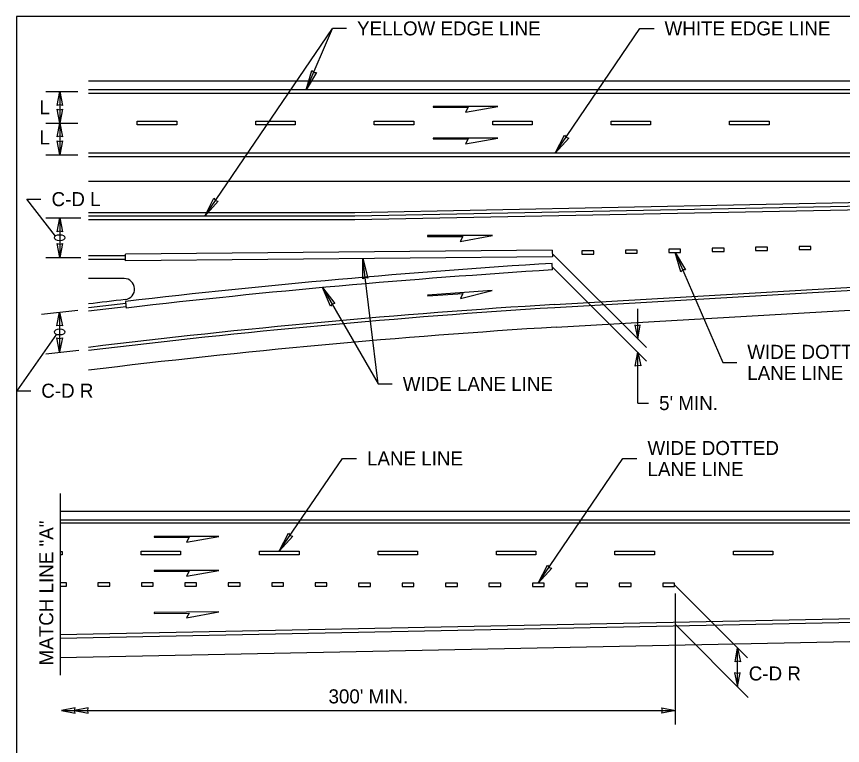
# Model space of a CAD drawing. Extents: x 99862 to 103151, y 100000 to 102076.
# Drawn here: x 99862 to 100803, y 101245 to 102076 of the extents above; entities that cross this region are included whole.
import ezdxf

# ---------------------------------------------------------------- set-up
doc = ezdxf.new("R2010")
doc.units = 0
for name, color, linetype in [('Level 1', 7, 'Continuous'), ('Level 15', 7, 'Continuous'), ('Level 2', 7, 'Continuous'), ('Level 20', 7, 'Continuous'), ('Level 3', 7, 'Continuous'), ('Level 4', 7, 'Continuous'), ('Level 5', 7, 'Continuous'), ('Level 6', 7, 'Continuous'), ('Level 7', 7, 'Continuous')]:
    doc.layers.add(name, color=color, linetype=linetype)

msp = doc.modelspace()

# ---------------------------------------------------------------- linework, layer by layer
at = {"layer": 'Level 1'}
msp.add_lwpolyline([(99862, 99999.5), (103151, 99999.5), (103151, 102075.5), (99862, 102075.5)], close=True, dxfattribs=at)
at = {"layer": 'Level 15'}
for p, q in [((100076.57, 101847.86), (100222.08, 102061.99)), ((100192.18, 101991.87), (100222.08, 102061.99)), ((100238.08, 102061.99), (100222.08, 102061.99)), ((100238.08, 102061.99), (100222.08, 102061.99)), ((100475.99, 101919.87), (100572.56, 102061.99)), ((100572.56, 102061.99), (100588.56, 102061.99)), ((100572.56, 102061.99), (100588.56, 102061.99)), ((99895.23, 101989.99), (99931.96, 101989.99)), ((99895.23, 101989.99), (99931.96, 101989.99)), ((99911.23, 101989.99), (99911.23, 101954.14)), ((99911.23, 101989.99), (99911.23, 101954.14)), ((99895.23, 101954.14), (99931.96, 101954.14)), ((99895.23, 101954.14), (99931.96, 101954.14)), ((99911.23, 101954.14), (99911.23, 101917.99)), ((99911.23, 101954.14), (99911.23, 101917.99)), ((99895.23, 101917.99), (99931.96, 101917.99)), ((99895.23, 101917.99), (99931.96, 101917.99)), ((99873.9, 101867.45), (99889.9, 101867.45)), ((99906.26, 101825.43), (99873.9, 101867.45)), ((99895.23, 101845.99), (99935.34, 101845.99)), ((99911.23, 101845.99), (99911.23, 101800.99)), ((99911.23, 101845.99), (99911.23, 101800.99)), ((100472.59, 101805.49), (100579.83, 101698.25)), ((100612.82, 101806.74), (100666.86, 101681.45)), ((99895.23, 101800.99), (99935.34, 101800.99)), ((100274.16, 101656.97), (100256.69, 101799.75)), ((100472.59, 101790.49), (100580.14, 101682.94)), ((100210.83, 101766.66), (100274.16, 101656.97)), ((99890.52, 101736.36), (99931.8, 101740.95)), ((100570.01, 101708.07), (100570.01, 101742.32)), ((99911.16, 101738.65), (99911.16, 101693.65)), ((99911.16, 101738.65), (99911.16, 101693.65)), ((99911.16, 101738.65), (99911.16, 101693.65)), ((99911.16, 101738.65), (99911.16, 101693.65)), ((99907.41, 101713.45), (99862.2, 101649.18)), ((99895.53, 101691.3), (99933.16, 101695.49)), ((100570.01, 101635.07), (100570.01, 101693.07)), ((100666.86, 101681.45), (100682.82, 101681.45)), ((100274.16, 101656.97), (100290.16, 101656.97)), ((100274.16, 101656.97), (100290.16, 101656.97)), ((99862.2, 101649.18), (99878.2, 101649.18)), ((100570.01, 101635.07), (100582.35, 101635.07)), ((100570.01, 101635.07), (100582.35, 101635.07)), ((100161.49, 101466.18), (100233.44, 101572.05)), ((100233.44, 101572.05), (100249.44, 101572.05)), ((100456.66, 101429.93), (100553.13, 101571.9)), ((100553.13, 101571.9), (100569.13, 101571.9)), ((100611.95, 101427.94), (100695.12, 101344.76)), ((100613.07, 101268.95), (100613.07, 101417.98)), ((100612.85, 101382.99), (100696.02, 101299.81)), ((100683.81, 101312.03), (100683.81, 101356.08)), ((99913.11, 101284.95), (100613.09, 101284.95))]:
    msp.add_line(p, q, dxfattribs=at)
for points in [[(100192.18, 101991.87), (100198.39, 102014.04), (100200.72, 102011.9), (100203.88, 102011.7)], [(99911.23, 101989.99), (99914.32, 101974.27), (99911.23, 101975), (99908.15, 101974.27)], [(99911.23, 101989.99), (99914.32, 101974.27), (99911.23, 101975), (99908.15, 101974.27)], [(99911.23, 101954.14), (99908.15, 101969.86), (99911.23, 101969.14), (99914.32, 101969.86)], [(99911.23, 101954.14), (99908.15, 101969.86), (99911.23, 101969.14), (99914.32, 101969.86)], [(99911.23, 101954.14), (99914.32, 101938.41), (99911.23, 101939.14), (99908.15, 101938.41)], [(99911.23, 101954.14), (99914.32, 101938.41), (99911.23, 101939.14), (99908.15, 101938.41)], [(100475.99, 101919.87), (100486.35, 101940.43), (100488.22, 101937.88), (100491.29, 101937.07)], [(100475.99, 101919.87), (100486.35, 101940.43), (100488.22, 101937.88), (100491.29, 101937.07)], [(99911.23, 101917.99), (99908.15, 101933.72), (99911.23, 101932.99), (99914.32, 101933.72)], [(99911.23, 101917.99), (99908.15, 101933.72), (99911.23, 101932.99), (99914.32, 101933.72)], [(100076.57, 101847.86), (100086.93, 101868.42), (100088.81, 101865.87), (100091.87, 101865.07)], [(99911.23, 101845.99), (99914.32, 101830.27), (99911.23, 101831), (99908.15, 101830.27)], [(99911.23, 101800.99), (99908.15, 101816.72), (99911.23, 101815.99), (99914.32, 101816.72)], [(100612.82, 101806.74), (100624.6, 101786.96), (100621.44, 101786.75), (100619.12, 101784.6)], [(100256.69, 101799.75), (100262.43, 101777.45), (100259.34, 101778.14), (100256.5, 101776.73)], [(100210.83, 101766.66), (100224.83, 101748.38), (100221.72, 101747.8), (100219.66, 101745.4)], [(99911.16, 101738.65), (99914.24, 101722.93), (99911.16, 101723.66), (99908.07, 101722.93)], [(99911.16, 101738.65), (99914.24, 101722.93), (99911.16, 101723.66), (99908.07, 101722.93)], [(100570.01, 101708.07), (100572.77, 101723.85), (100569.71, 101723.06), (100566.61, 101723.73)], [(99911.16, 101693.65), (99908.07, 101709.38), (99911.16, 101708.65), (99914.24, 101709.38)], [(99911.16, 101693.65), (99908.07, 101709.38), (99911.16, 101708.65), (99914.24, 101709.38)], [(100570.01, 101693.07), (100573.4, 101677.41), (100570.31, 101678.07), (100567.24, 101677.28)], [(100161.49, 101466.18), (100171.86, 101486.74), (100173.73, 101484.19), (100176.79, 101483.38)], [(100456.65, 101429.93), (100467.01, 101450.49), (100468.88, 101447.93), (100471.95, 101447.13)], [(100683.81, 101356.08), (100687.21, 101340.42), (100684.11, 101341.08), (100681.04, 101340.29)], [(100683.81, 101312.03), (100686.58, 101327.81), (100683.51, 101327.02), (100680.41, 101327.69)], [(99913.11, 101284.95), (99928.84, 101281.86), (99928.11, 101284.95), (99928.84, 101288.03)], [(99913.11, 101284.95), (99928.84, 101281.86), (99928.11, 101284.95), (99928.84, 101288.03)], [(99928.11, 101284.95), (99943.83, 101281.86), (99943.11, 101284.95), (99943.83, 101288.03)], [(99928.11, 101284.95), (99943.83, 101281.86), (99943.11, 101284.95), (99943.83, 101288.03)], [(100613.09, 101284.95), (100597.36, 101281.86), (100598.09, 101284.95), (100597.36, 101288.03)], [(100613.09, 101284.95), (100597.36, 101281.86), (100598.09, 101284.95), (100597.36, 101288.03)]]:
    msp.add_lwpolyline(points, close=True, dxfattribs=at)
for centre in [(99911.23, 101823.49), (99911.16, 101716.15), (99911.16, 101716.15)]:
    msp.add_ellipse(centre, major_axis=(-6, 0), ratio=0.57735, dxfattribs=at)
at = {"layer": 'Level 2'}
for p, q in [((103122.6, 102001.99), (99943.96, 102001.99)), ((99943.96, 101887.99), (100847.47, 101887.99)), ((100476.85, 101721.62), (102047.59, 101812.88)), ((99984.6, 101776.99), (99943.96, 101776.99)), ((99911.91, 101512.05), (103093.21, 101512.05))]:
    msp.add_line(p, q, dxfattribs=at)
for points in [[(100847.71, 101864), (100247.59, 101851.99), (99943.96, 101851.99)], [(103091.68, 101403.93), (102836.68, 101403.93), (99911.91, 101344.93)]]:
    msp.add_lwpolyline(points, dxfattribs=at)
for centre, radius, start, end in [((99984.6, 101764.99), 12, 276.65498, 90), ((101029.01, 92813.72), 9000, 96.654983, 96.924425), ((101029.01, 92813.72), 8925, 93.546909, 96.982902)]:
    msp.add_arc(centre, radius, start, end, dxfattribs=at)
at = {"layer": 'Level 3'}
for p, q in [((103122.6, 101991.87), (99943.96, 101991.87)), ((103122.6, 101991.87), (99943.96, 101991.87)), ((99943.96, 101988.12), (103122.6, 101988.12)), ((100472.51, 101809.24), (99986.25, 101804.74)), ((100472.51, 101809.24), (100472.82, 101801.75)), ((100472.51, 101809.24), (100472.82, 101801.75)), ((99986.25, 101797.25), (99986.25, 101804.74)), ((99986.25, 101797.25), (99986.25, 101804.74)), ((100472.82, 101801.75), (99986.25, 101797.25)), ((100472.82, 101786.74), (100472.35, 101794.23)), ((99943.96, 101743.91), (99986.47, 101748.97)), ((99943.96, 101743.91), (99986.47, 101748.97)), ((99986.25, 101750.84), (99987.12, 101743.39)), ((99943.96, 101740.14), (99986.9, 101745.26)), ((99943.96, 101740.14), (99986.9, 101745.26)), ((99911.91, 101501.93), (103093.21, 101501.93)), ((103093.21, 101498.18), (99911.91, 101498.18))]:
    msp.add_line(p, q, dxfattribs=at)
msp.add_lwpolyline([(99943.96, 101844.12), (100247.62, 101844.12), (100847.86, 101856.13), (100847.79, 101859.87), (100247.55, 101847.86), (99943.96, 101847.86)], dxfattribs=at)
for radius in [8997.75, 8990.25]:
    msp.add_arc((101029.01, 92813.72), radius, 93.546909, 96.654983, dxfattribs=at)
at = {"layer": 'Level 4'}
for p, q in [((100847.9, 101919.87), (99943.96, 101919.87)), ((99943.96, 101916.12), (100847.9, 101916.12))]:
    msp.add_line(p, q, dxfattribs=at)
for points in [[(99999.68, 101956.12), (100044.68, 101956.11), (100044.68, 101952.15), (99999.68, 101952.16)], [(100134.68, 101956.12), (100179.68, 101956.11), (100179.68, 101952.15), (100134.68, 101952.16)], [(100269.68, 101956.12), (100314.68, 101956.11), (100314.68, 101952.15), (100269.68, 101952.16)], [(100404.68, 101956.12), (100449.68, 101956.11), (100449.68, 101952.15), (100404.68, 101952.16)], [(100539.68, 101956.12), (100584.68, 101956.11), (100584.68, 101952.15), (100539.68, 101952.16)], [(100674.68, 101956.12), (100719.68, 101956.11), (100719.68, 101952.15), (100674.68, 101952.16)], [(100506.42, 101804.66), (100519.92, 101804.66), (100519.92, 101808.41), (100506.42, 101808.41)], [(100506.42, 101804.66), (100519.92, 101804.66), (100519.92, 101808.41), (100506.42, 101808.41)], [(100555.91, 101805.71), (100569.41, 101805.71), (100569.41, 101809.46), (100555.91, 101809.46)], [(100555.91, 101805.71), (100569.41, 101805.71), (100569.41, 101809.46), (100555.91, 101809.46)], [(100605.4, 101806.75), (100618.9, 101806.75), (100618.9, 101810.5), (100605.4, 101810.5)], [(100605.4, 101806.75), (100618.9, 101806.75), (100618.9, 101810.5), (100605.4, 101810.5)], [(100654.89, 101807.8), (100668.39, 101807.8), (100668.39, 101811.55), (100654.89, 101811.55)], [(100654.89, 101807.8), (100668.39, 101807.8), (100668.39, 101811.55), (100654.89, 101811.55)], [(100704.38, 101808.84), (100717.88, 101808.84), (100717.88, 101812.59), (100704.38, 101812.59)], [(100704.38, 101808.84), (100717.88, 101808.84), (100717.88, 101812.59), (100704.38, 101812.59)], [(100753.87, 101809.89), (100767.37, 101809.89), (100767.37, 101813.64), (100753.87, 101813.64)], [(100753.87, 101809.89), (100767.37, 101809.89), (100767.37, 101813.64), (100753.87, 101813.64)], [(100003.99, 101466.18), (100048.99, 101466.18), (100048.99, 101462.2), (100003.99, 101462.2)], [(100138.99, 101466.18), (100183.99, 101466.18), (100183.99, 101462.2), (100138.99, 101462.2)], [(100273.99, 101466.18), (100318.99, 101466.18), (100318.99, 101462.2), (100273.99, 101462.2)], [(100408.99, 101466.18), (100453.99, 101466.18), (100453.99, 101462.2), (100408.99, 101462.2)], [(100543.99, 101466.18), (100588.99, 101466.18), (100588.99, 101462.2), (100543.99, 101462.2)], [(100678.99, 101466.18), (100723.99, 101466.18), (100723.99, 101462.2), (100678.99, 101462.2)], [(99954.79, 101426.4), (99968.29, 101426.4), (99968.29, 101430.15), (99954.79, 101430.15)], [(99954.79, 101426.4), (99968.29, 101426.4), (99968.29, 101430.15), (99954.79, 101430.15)], [(100004.29, 101426.4), (100017.79, 101426.4), (100017.79, 101430.15), (100004.29, 101430.15)], [(100004.29, 101426.4), (100017.79, 101426.4), (100017.79, 101430.15), (100004.29, 101430.15)], [(100053.79, 101426.4), (100067.29, 101426.4), (100067.29, 101430.15), (100053.79, 101430.15)], [(100053.79, 101426.4), (100067.29, 101426.4), (100067.29, 101430.15), (100053.79, 101430.15)], [(100103.31, 101426.4), (100116.81, 101426.45), (100116.79, 101430.2), (100103.29, 101430.15)], [(100103.31, 101426.4), (100116.81, 101426.45), (100116.79, 101430.2), (100103.29, 101430.15)], [(100152.79, 101426.4), (100166.29, 101426.4), (100166.29, 101430.15), (100152.79, 101430.15)], [(100152.79, 101426.4), (100166.29, 101426.4), (100166.29, 101430.15), (100152.79, 101430.15)], [(100202.29, 101426.4), (100215.79, 101426.4), (100215.79, 101430.15), (100202.29, 101430.15)], [(100202.29, 101426.4), (100215.79, 101426.4), (100215.79, 101430.15), (100202.29, 101430.15)], [(100251.9, 101426.18), (100265.4, 101426.18), (100265.4, 101429.93), (100251.9, 101429.93)], [(100251.9, 101426.18), (100265.4, 101426.18), (100265.4, 101429.93), (100251.9, 101429.93)], [(100301.4, 101426.18), (100314.9, 101426.18), (100314.9, 101429.93), (100301.4, 101429.93)], [(100350.9, 101426.18), (100364.4, 101426.18), (100364.4, 101429.93), (100350.9, 101429.93)], [(100350.9, 101426.18), (100364.4, 101426.18), (100364.4, 101429.93), (100350.9, 101429.93)], [(100400.4, 101426.18), (100413.9, 101426.18), (100413.9, 101429.93), (100400.4, 101429.93)], [(100400.4, 101426.18), (100413.9, 101426.18), (100413.9, 101429.93), (100400.4, 101429.93)], [(100449.9, 101426.18), (100463.4, 101426.18), (100463.4, 101429.93), (100449.9, 101429.93)], [(100449.9, 101426.18), (100463.4, 101426.18), (100463.4, 101429.93), (100449.9, 101429.93)], [(100499.41, 101426.17), (100512.91, 101426.22), (100512.9, 101429.97), (100499.4, 101429.92)], [(100499.41, 101426.17), (100512.91, 101426.22), (100512.9, 101429.97), (100499.4, 101429.92)], [(100548.9, 101426.18), (100562.4, 101426.18), (100562.4, 101429.93), (100548.9, 101429.93)], [(100548.9, 101426.18), (100562.4, 101426.18), (100562.4, 101429.93), (100548.9, 101429.93)], [(100598.4, 101426.18), (100611.9, 101426.18), (100611.9, 101429.93), (100598.4, 101429.93)], [(100598.4, 101426.18), (100611.9, 101426.18), (100611.9, 101429.93), (100598.4, 101429.93)]]:
    msp.add_lwpolyline(points, close=True, dxfattribs=at)
for points in [[(100475.09, 101747.43), (102048.78, 101838.86), (103122.6, 101860.84)], [(103122.6, 101857.1), (102049, 101835.13), (100475.48, 101743.71)], [(99986.25, 101802.86), (99943.96, 101802.86)], [(99986.25, 101802.86), (99943.96, 101802.86)], [(99943.96, 101799.12), (99986.25, 101799.12)], [(99943.96, 101799.12), (99986.25, 101799.12)], [(99911.91, 101466.17), (99913.99, 101466.16), (99913.99, 101462.2), (99911.91, 101462.21)], [(99911.91, 101466.17), (99913.99, 101466.16), (99913.99, 101462.2), (99911.91, 101462.21)], [(99911.91, 101426.4), (99918.79, 101426.4), (99918.79, 101430.15), (99911.91, 101430.15)], [(99911.91, 101426.4), (99918.79, 101426.4), (99918.79, 101430.15), (99911.91, 101430.15)], [(103093.21, 101429.92), (102838.17, 101429.92), (99911.91, 101370.9)]]:
    msp.add_lwpolyline(points, dxfattribs=at)
for centre, radius, start, end in [((101029.04, 92813.35), 8951.24, 93.548082, 96.962585), ((101029.01, 92813.72), 8947.13, 93.546909, 96.965545)]:
    msp.add_arc(centre, radius, start, end, dxfattribs=at)
at = {"layer": 'Level 5'}
for points in [[(100336.8, 101972.12), (100376.87, 101972.12), (100373.72, 101966.65), (100410.63, 101973.16), (100336.8, 101973.16)], [(100336.8, 101936.01), (100376.87, 101936.01), (100373.72, 101930.55), (100410.63, 101937.06), (100336.8, 101937.06)], [(100330.55, 101824.83), (100370.62, 101824.83), (100367.46, 101819.36), (100404.38, 101825.87), (100330.55, 101825.87)], [(100330.61, 101757.15), (100370.58, 101759.95), (100367.82, 101754.27), (100404.19, 101763.35), (100330.54, 101758.19)], [(100018.77, 101482.18), (100058.84, 101482.18), (100055.69, 101476.71), (100092.6, 101483.22), (100018.77, 101483.22)], [(100018.77, 101482.18), (100058.84, 101482.18), (100055.69, 101476.71), (100092.6, 101483.22), (100018.77, 101483.22)], [(100018.77, 101443.48), (100058.84, 101443.48), (100055.69, 101438.01), (100092.6, 101444.52), (100018.77, 101444.52)], [(100018.77, 101443.48), (100058.84, 101443.48), (100055.69, 101438.01), (100092.6, 101444.52), (100018.77, 101444.52)], [(100018.79, 101395.33), (100058.86, 101395.9), (100055.78, 101390.39), (100092.6, 101397.43), (100018.78, 101396.38)], [(100018.79, 101395.33), (100058.86, 101395.9), (100055.78, 101390.39), (100092.6, 101397.43), (100018.78, 101396.38)]]:
    msp.add_lwpolyline(points, close=True, dxfattribs=at)
at = {"layer": 'Level 6'}
msp.add_line((99911.91, 101532.05), (99911.91, 101324.93), dxfattribs=at)
at = {"layer": 'Level 7'}
msp.add_lwpolyline([(99911.91, 101367.15), (102838.24, 101426.18), (103093.21, 101426.18)], dxfattribs=at)

# ---------------------------------------------------------------- texts
at = {"layer": 'Level 20'}
for s, p in [('YELLOW EDGE LINE', (100250.08, 102053.99)), ('WHITE EDGE LINE', (100600.56, 102053.99)), ('L', (99888.13, 101964.07)), ('L', (99888.13, 101929.75)), ('C-D L', (99901.9, 101859.45)), ('WIDE DOTTED', (100694.82, 101685.45)), ('LANE LINE', (100694.82, 101661.45)), ('WIDE LANE LINE', (100302.16, 101648.97)), ('C-D R', (99890.2, 101641.18)), ("5' MIN.", (100594.35, 101627.07)), ('WIDE DOTTED ', (100581.13, 101575.9)), ('LANE LINE', (100261.44, 101564.05)), ('LANE LINE', (100581.13, 101551.9)), ('C-D R', (100696.53, 101319.02)), ("300' MIN.", (100217.55, 101292.95))]:
    msp.add_text(s, height=16, dxfattribs=at).set_placement(p)
msp.add_text('MATCH LINE "A"', height=16, rotation=90, dxfattribs=at).set_placement((99903.91, 101336.2))

doc.saveas('drawing.dxf')
